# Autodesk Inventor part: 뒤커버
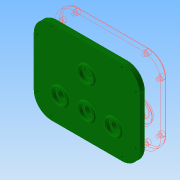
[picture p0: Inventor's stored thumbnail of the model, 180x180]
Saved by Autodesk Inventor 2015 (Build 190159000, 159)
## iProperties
Created: 2016-12
Part Number: 뒤커버
Material: 알루미늄 6061
Document SubType Name: Modeling
Designer: mduedu
Density: 2.71 g/cm^3
Mass: 671.677 g
Surface Area: 613.699 cm^2
Volume: 247.851 cm^3
Appearance: 진녹색
Author: mduedu
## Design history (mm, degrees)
sketch "스케치1"
  geometry: L1 (-90, 42)-(-90, -42); L2 (-60, 72)-(60, 72); L3 (90, 42)-(90, -42); L4 (60, -72)-(-60, -72); A1 r 30 centre (-60, -42) between (-90, -42) and (-60, -72); A2 r 30 centre (60, 42) between (90, 42) and (60, 72); A3 r 30 centre (60, -42) between (60, -72) and (90, -42); A4 r 30 centre (-60, 42) between (-60, 72) and (-90, 42); 1 further point
  constraints: 8 end point, 8 point on circle, 8 tangent, 4 centre point, 3 equal radius, 2 perpendicular, 1 horizontal, 1 vertical
  dimensions: "d80" = 30 radius of A2; "d81" = 144 distance between parallel lines of L4 L2; "d115" = 72 distance from line of L2 point (0, 0); "d116" = 90 distance from line of point (0, 0) L1; "d117" = 180 distance between parallel lines of L3 L1
extrude "돌출1" new body sketch "스케치1" distance "d3" = 10; taper "d4" = 0 deg
sketch "스케치2"
  geometry: C1 r 14 at (0, 26); 1 further point
  constraints: 1 centre point, 1 vertical alignment
  dimensions: "d5" = 28 diameter of C1; "d6" = 26 distance of C1.centre point (0, 0)
extrude "돌출2" join sketch "스케치2" distance "d7" = 3; taper "d8" = 0 deg
sketch "스케치3"
  geometry: C1 r 14 at (0, -28.87); C2 r 14 at (0, 26) reference; C3 r 14 at (-45.552, -28.87); C4 r 14 at (45.552, -28.87); 1 further point
  constraints: 3 centre point, 2 equal radius, 2 horizontal alignment, 1 vertical alignment
  dimensions: "d9" = 28 diameter of C1; "d69" = 54.87 distance of C1.centre C2.centre; "d118" = 45.552 distance of C3.centre C1.centre; "d119" = 45.552 distance of C4.centre C1.centre
extrude "돌출3" join sketch "스케치3" distance "d11" = 3; taper "d12" = 0 deg
hole "구멍1" diameter "d15" = 22; stored, may be unused: countersink angle "d19" = 90 deg, drill point angle "d21" = 0 deg; dims "d13" = 10, "d14" = 10, "d16" = 6, "d17" = 4, "d18" = 2, "d20" = 7
hole "구멍2" diameter "d24" = 18; stored, may be unused: countersink angle "d28" = 90 deg, drill point angle "d30" = 0 deg; dims "d22" = 10, "d23" = 10, "d25" = 6, "d26" = 4, "d27" = 2, "d29" = 1
hole "구멍3" diameter "d33" = 22; stored, may be unused: countersink angle "d37" = 90 deg, drill point angle "d39" = 0 deg; dims "d31" = 10, "d32" = 10, "d34" = 6, "d35" = 4, "d36" = 2, "d38" = 7
hole "구멍7" diameter "d87" = 22; stored, may be unused: countersink angle "d91" = 90 deg, drill point angle "d93" = 0 deg; dims "d88" = 6, "d89" = 4, "d90" = 2, "d92" = 7, "d120" = 10, "d121" = 10
hole "구멍10" diameter "d124" = 22; stored, may be unused: countersink angle "d128" = 90 deg, drill point angle "d130" = 0 deg; dims "d122" = 10, "d123" = 10, "d125" = 6, "d126" = 4, "d127" = 2, "d129" = 7
sketch "스케치4"
  geometry: C1 r 14 at (0, -28.87) reference; C2 r 18 at (0, -28.87); C3 r 14 at (-45.552, -28.87) reference; C4 r 14 at (45.552, -28.87) reference; C5 r 18 at (-45.552, -28.87); C6 r 18 at (45.552, -28.87); 1 further point
  constraints: 3 centre point, 3 coincident
  dimensions: "d40" = 36 diameter of C2; "d131" = 36 diameter of C5; "d132" = 36 diameter of C6
extrude "돌출4" join sketch "스케치4" distance "d41" = 4; taper "d42" = 0 deg
hole "구멍4" diameter "d45" = 22; stored, may be unused: countersink angle "d49" = 90 deg, drill point angle "d51" = 0 deg; dims "d46" = 6, "d47" = 4, "d48" = 2, "d50" = 7.3, "d144" = 10, "d145" = 10
hole "구멍8" diameter "d97" = 22; stored, may be unused: countersink angle "d101" = 90 deg, drill point angle "d103" = 0 deg; dims "d98" = 6, "d99" = 4, "d100" = 2, "d102" = 7.3, "d146" = 10, "d147" = 10
hole "구멍11" diameter "d137" = 22; stored, may be unused: countersink angle "d141" = 90 deg, drill point angle "d143" = 0 deg; dims "d138" = 6, "d139" = 4, "d140" = 2, "d142" = 7.3, "d148" = 10, "d149" = 10
hole "구멍5" diameter "d54" = 15; stored, may be unused: countersink angle "d58" = 90 deg, drill point angle "d60" = 0 deg; dims "d55" = 6, "d56" = 4, "d57" = 2, "d59" = 7, "d150" = 10, "d151" = 10
hole "구멍9" diameter "d106" = 15; stored, may be unused: countersink angle "d110" = 90 deg, drill point angle "d112" = 0 deg; dims "d107" = 6, "d108" = 4, "d109" = 2, "d111" = 7, "d152" = 10, "d153" = 10
hole "구멍12" diameter "d156" = 15; stored, may be unused: countersink angle "d160" = 90 deg, drill point angle "d162" = 0 deg; dims "d154" = 10, "d155" = 10, "d157" = 6, "d158" = 4, "d159" = 2, "d161" = 7
fillet "모깎기1" dims "d61" = 0.3
fillet "모깎기2" dims "d62" = 2
chamfer "모따기1" distance "d63" = 1; stored, may be unused: second distance "d64" = 2, angle "d65" = 45 deg
chamfer "모따기2" distance "d163" = 0.7; stored, may be unused: second distance "d164" = 2, angle "d165" = 30 deg
chamfer "모따기3" distance "d166" = 0.7; stored, may be unused: second distance "d167" = 2, angle "d168" = 30 deg
chamfer "모따기4" distance "d169" = 0.7; stored, may be unused: second distance "d170" = 2, angle "d171" = 30 deg
fillet "모깎기3" dims "d66" = 2
fillet "모깎기4" dims "d67" = 2
fillet "모깎기6" dims "d172" = 2
sketch "스케치5"
  geometry: L1 (-60, 72)-(60, 72) reference; L2 (-90, -42)-(-90, 42) reference; L3 (60, -72)-(-60, -72) reference; L4 (90, 42)-(90, -42) reference; L5 (60, 66)-(-60, 66); L6 (-84, 42)-(-84, -42); L7 (-60, -66)-(60, -66); L8 (84, -42)-(84, 42); A1 r 30 centre (-60, 42) between (-60, 72) and (-90, 42) reference; A2 r 30 centre (-60, -42) between (-90, -42) and (-60, -72) reference; A3 r 30 centre (60, -42) between (60, -72) and (90, -42) reference; A4 r 30 centre (60, 42) between (90, 42) and (60, 72) reference; A5 r 24 centre (-60, 42) between (-60, 66) and (-84, 42); A6 r 24 centre (-60, -42) between (-84, -42) and (-60, -66); A7 r 24 centre (60, -42) between (60, -66) and (84, -42); A8 r 24 centre (60, 42) between (84, 42) and (60, 66)
  constraints: 8 end point, 8 point on circle, 4 centre point, 7 other
  dimensions: "d113" = 6 distance between parallel lines of L6 L2
sketch "스케치6"
  geometry: L1 (60, 66)-(-60, 66) reference; L2 (84, -42)-(84, 42) reference; L3 (-60, -66)-(60, -66) reference; L4 (-84, 42)-(-84, -42) reference; A1 r 24 centre (60, 42) between (84, 42) and (60, 66) reference; A2 r 24 centre (60, -42) between (60, -66) and (84, -42) reference; A3 r 24 centre (-60, -42) between (-84, -42) and (-60, -66) reference; A4 r 24 centre (-60, 42) between (-60, 66) and (-84, 42) reference; 8 further points
  constraints: 8 coincident
hole "구멍6" sketch "스케치6" at (-60, 66), (-84, 42), (-84, -42), (-60, -66), (60, -66), (84, -42), (84, 42), (60, 66) diameter "d71" = 4.5; stored, may be unused: countersink angle "d75" = 90 deg, drill point angle "d77" = 0 deg; dims "d72" = 6, "d73" = 8, "d74" = 4.6, "d76" = 8
node "솔리드1"
